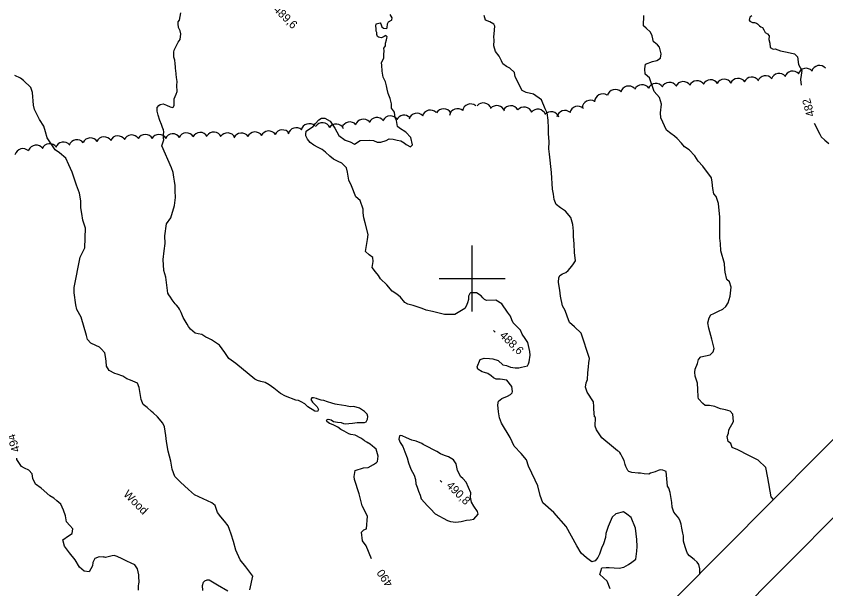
# Model space of a CAD drawing. Extents: x 642515 to 647219, y 6080136 to 6084356.
# Drawn here: x 644234.2 to 644528.9, y 6080687.3 to 6080895.6 of the extents above; entities that cross this region are included whole.
import ezdxf

# ---------------------------------------------------------------- set-up
doc = ezdxf.new("R2010")
doc.units = 0
for name, color, linetype in [('Level 1', 7, 'Continuous'), ('Level 2', 7, 'Continuous'), ('Level 3', 7, 'Continuous'), ('Level 44', 7, 'Continuous'), ('Level 60', 7, 'Continuous'), ('Level 61', 7, 'Continuous')]:
    doc.layers.add(name, color=color, linetype=linetype)

msp = doc.modelspace()

# ---------------------------------------------------------------- linework, layer by layer
at = {"layer": 'Level 1'}
for points in [[(644292.11, 6080878.36), (644291.9, 6080879.6), (644291.55, 6080880.67), (644291.57, 6080881.56), (644291.61, 6080881.6), (644291.63, 6080882.49), (644291.7, 6080883.26), (644293.17, 6080886.15), (644293.91, 6080887.16), (644294.09, 6080889.2), (644293.9, 6080890.28), (644293.33, 6080891.53), (644293.13, 6080892.85), (644293.2, 6080893.62), (644293.65, 6080894.14), (644294.16, 6080896.8)], [(644289.44, 6080794.85), (644288.65, 6080800.7), (644287.92, 6080803.15), (644287.74, 6080807.1), (644288.02, 6080810.19), (644288.4, 6080812.88), (644288.3, 6080815.7), (644288.9, 6080820.02), (644290.53, 6080822.23), (644291.77, 6080826.75), (644292.22, 6080829.69), (644292.06, 6080832.11), (644292.09, 6080834.05), (644291.82, 6080835.64), (644291.57, 6080837.08), (644291.38, 6080838.77), (644290.78, 6080840.5), (644287.22, 6080848.46), (644287.88, 6080850.69), (644287.8, 6080851.21), (644287.83, 6080852.63), (644287.9, 6080853.4), (644287.79, 6080854.4), (644287.61, 6080854.79), (644287.11, 6080856.21), (644286.52, 6080857.71), (644285.83, 6080859.6), (644285.49, 6080861.11), (644285.57, 6080862.41), (644286.08, 6080863.17), (644286.62, 6080863.53), (644287.7, 6080863.73), (644288.95, 6080863.24), (644290.2, 6080862.68), (644291.18, 6080862.42), (644291.49, 6080862.61), (644291.65, 6080863.3), (644291.69, 6080864.56), (644291.66, 6080865.57), (644292.48, 6080867.2), (644292.78, 6080868.22), (644292.67, 6080870.44), (644292.74, 6080871.9), (644292.52, 6080873.38), (644292.4, 6080874.54), (644292.39, 6080874.7), (644292.31, 6080875.83), (644292.22, 6080876.59), (644292.15, 6080877.11), (644292.11, 6080878.36)], [(644349.02, 6080754.76), (644347.45, 6080755.3), (644346.16, 6080755.74), (644345.22, 6080755.96), (644344.44, 6080756.11), (644343.7, 6080756.38), (644343.45, 6080756.53), (644342.42, 6080756.74), (644341.85, 6080756.78), (644341.49, 6080756.19), (644342.04, 6080755.18), (644342.99, 6080754.27), (644343.77, 6080753.44), (644344.2, 6080752.46), (644343.92, 6080751.79), (644342.9, 6080751.93), (644340.38, 6080753.45), (644339.21, 6080754.63), (644337.95, 6080755.35), (644336.95, 6080755.77), (644335.93, 6080755.9), (644332.16, 6080757.39), (644330.36, 6080758.28), (644327.97, 6080760.22), (644326.31, 6080761.52), (644324.84, 6080762.35), (644323.24, 6080762.69), (644322.05, 6080763.06), (644321.04, 6080763.56), (644314.16, 6080769.2), (644311.61, 6080771.13), (644310.18, 6080773.29), (644308.14, 6080775.98), (644305.23, 6080777.85), (644304.1, 6080778.46), (644303.18, 6080778.88), (644301.75, 6080779.76), (644300.48, 6080780.04), (644299.37, 6080780.33), (644297.66, 6080781.75), (644296.87, 6080782.74), (644296.4, 6080783.6), (644294.95, 6080786.01), (644294.27, 6080787.82), (644293.62, 6080788.99), (644293.3, 6080789.58), (644292.59, 6080790.5), (644292.04, 6080790.99), (644290.97, 6080792.45), (644290.42, 6080793.38), (644289.76, 6080794.27), (644289.44, 6080794.85)], [(644366, 6080735.57), (644365.19, 6080738.1), (644364.5, 6080738.71), (644363.9, 6080739.23), (644363.01, 6080739.86), (644362.42, 6080740.22), (644362.34, 6080740.3), (644361.83, 6080740.59), (644360.95, 6080741.13), (644360.4, 6080741.54), (644359.67, 6080742.1), (644357.58, 6080743.17), (644356.03, 6080743.39), (644355.21, 6080743.66), (644353.61, 6080744.6), (644352.39, 6080745.29), (644351.21, 6080746.1), (644349.82, 6080746.85), (644348.99, 6080747.2), (644348.29, 6080747.44), (644347.2, 6080748.09), (644347.14, 6080748.37), (644347.39, 6080748.83), (644347.79, 6080748.94), (644348.31, 6080748.93), (644348.8, 6080748.81), (644349.69, 6080748.18), (644351.16, 6080747.95), (644352.43, 6080747.76), (644353.34, 6080747.41), (644354.12, 6080747.26), (644355.24, 6080747.42), (644356.6, 6080747.59), (644358.32, 6080747.83), (644359.45, 6080747.82), (644359.82, 6080747.8), (644360.91, 6080747.76), (644361.54, 6080748.04), (644362.08, 6080749), (644362.14, 6080750.02), (644361.88, 6080750.85), (644361.01, 6080751.76), (644359.15, 6080753.01), (644357.14, 6080753.56), (644355.73, 6080753.51), (644354.17, 6080753.81), (644352.65, 6080754.15), (644351.02, 6080754.37), (644350.29, 6080754.48), (644349.02, 6080754.76)], [(644394.87, 6080730.31), (644394.39, 6080732.7), (644393.32, 6080734.24), (644391.48, 6080735.25), (644390.07, 6080735.72), (644388.57, 6080736.43), (644387.3, 6080737.24), (644385.8, 6080737.94), (644384.29, 6080738.81), (644382.29, 6080739.81), (644381.78, 6080740.1), (644379.79, 6080740.94), (644378.22, 6080741.4), (644376.23, 6080742.23), (644374.73, 6080742.94), (644374.23, 6080743.07), (644373.76, 6080742.88), (644373.51, 6080741.73), (644374, 6080740.55), (644374.91, 6080738.99), (644375.68, 6080737.11), (644376.55, 6080734.98), (644377, 6080733.08), (644377.87, 6080730.79), (644378.99, 6080728.6), (644379.58, 6080727.03), (644379.68, 6080725.42), (644380.17, 6080724.24), (644380.67, 6080722.74), (644381.25, 6080721.32), (644381.65, 6080720.06), (644383.93, 6080717.46), (644385.05, 6080716.33), (644386.63, 6080714.49), (644391.23, 6080712.13), (644392.3, 6080711.8), (644394.18, 6080711.52), (644396.18, 6080711.74), (644398.09, 6080712.19), (644399.46, 6080712.36), (644400.73, 6080712.61), (644402.31, 6080714.41), (644402.08, 6080715.36), (644400.82, 6080717.38), (644399.92, 6080718.77), (644399.56, 6080720.61), (644399.7, 6080722.15), (644397.98, 6080726.07), (644396.76, 6080727.45), (644396.07, 6080728.05), (644394.87, 6080730.31)], [(644363.48, 6080698.23), (644361.62, 6080702.89), (644360.21, 6080704.74), (644359.92, 6080707.87), (644360.67, 6080708.72), (644361.7, 6080709.04), (644362.12, 6080713.67), (644360.1, 6080717.41), (644358.99, 6080721.86), (644357.35, 6080727.08), (644357.2, 6080728.12), (644357.62, 6080730.33), (644360.55, 6080731.25), (644362.32, 6080731.37), (644364.26, 6080732.55), (644365.35, 6080733.27), (644365.73, 6080733.54), (644366, 6080735.57)]]:
    msp.add_lwpolyline(points, dxfattribs=at)
at = {"layer": 'Level 2'}
for points in [[(644372.13, 6080858.65), (644371.83, 6080860.74), (644370.84, 6080862.21), (644370.82, 6080863.75), (644370.37, 6080865.66), (644369.6, 6080867.55), (644369.26, 6080869.06), (644368.93, 6080870.26), (644368.59, 6080871.77), (644367.75, 6080873.41), (644367.44, 6080875.66), (644367.3, 6080877.75), (644367.17, 6080878.63), (644368.06, 6080880.43), (644368.05, 6080881.2), (644368.02, 6080881.69), (644368.09, 6080883.07), (644368.02, 6080884.03), (644368.4, 6080884.46), (644368.61, 6080884.88), (644368.67, 6080885.82), (644368.92, 6080886.97), (644369.08, 6080887.66), (644369.17, 6080888.11), (644368.69, 6080888.61), (644368.1, 6080888.29), (644367.21, 6080887.78), (644366.55, 6080887.9), (644366.1, 6080887.99), (644365.64, 6080888.24), (644365.51, 6080888.96), (644365.42, 6080889.73), (644365.23, 6080890.2), (644365.2, 6080891.21), (644365.1, 6080892.05), (644365.17, 6080892.83), (644366.73, 6080893.21), (644366.95, 6080892.86), (644367.16, 6080892.15), (644367.31, 6080891.71), (644367.91, 6080891.27), (644368.92, 6080891.21), (644369.23, 6080891.4), (644369.3, 6080892.86), (644369.66, 6080893.53), (644370.79, 6080894.13), (644370.94, 6080894.3), (644371.01, 6080895.08), (644370.25, 6080896.2)], [(644428.05, 6080847.41), (644428.13, 6080849.93), (644427.93, 6080853), (644427.89, 6080854.86), (644427.85, 6080857.77), (644427.44, 6080860.42), (644426.77, 6080861.91), (644425.42, 6080865.23), (644422.45, 6080867.22), (644419.81, 6080867.85), (644418.38, 6080868.65), (644415.86, 6080873.59), (644415.52, 6080875.11), (644413.87, 6080876.7), (644412.62, 6080877.34), (644411.34, 6080878.31), (644410.78, 6080879.41), (644409.94, 6080881.05), (644408.69, 6080882.75), (644408.07, 6080884.82), (644408.18, 6080886.85), (644408.09, 6080888.15), (644408.1, 6080889.2), (644408.4, 6080891.98), (644408.03, 6080892.76), (644406.6, 6080893.56), (644405.02, 6080894.18), (644404.58, 6080895.85)], [(644462.51, 6080892.12), (644462.59, 6080895.86)], [(644501.9, 6080895.82), (644501.16, 6080895.32), (644500.94, 6080894.21), (644501.25, 6080893.87), (644501.72, 6080893.53), (644502.22, 6080893.32), (644502.91, 6080893.33), (644503.62, 6080893.09), (644504, 6080892.83), (644504.7, 6080892.14), (644505.17, 6080891.81), (644505.76, 6080891.52), (644506.26, 6080890.7), (644506.81, 6080889.68), (644507.58, 6080889.17), (644508.24, 6080888.44), (644508.13, 6080887.09), (644508.53, 6080885.81), (644508.64, 6080884.2), (644509.66, 6080883.61), (644510.38, 6080883.74), (644512.38, 6080883.06), (644513.53, 6080882.81), (644514.85, 6080882.58), (644517.49, 6080881.94), (644518.54, 6080880.87), (644518.97, 6080878.05), (644520.09, 6080875.85), (644519.88, 6080874.21), (644519.66, 6080872.57), (644519.92, 6080870.49)], [(644509.86, 6080719.79), (644509, 6080720.78), (644507.73, 6080727.67), (644507, 6080731.36), (644504.22, 6080734.09), (644500.86, 6080735.82), (644496.83, 6080737.82), (644494.83, 6080738.66), (644494.25, 6080740.09), (644493.38, 6080740.84), (644493.02, 6080742.68), (644493.43, 6080743.85), (644493.59, 6080745.07), (644495.25, 6080748.19), (644495, 6080750.85), (644494.11, 6080751.93), (644492.38, 6080752.38), (644490.57, 6080752.75), (644489.56, 6080753.17), (644488.48, 6080753.66), (644486.59, 6080753.94), (644484.96, 6080754), (644484.1, 6080754.75), (644482.53, 6080756.43), (644482.4, 6080757.15), (644482.3, 6080759.82), (644482.15, 6080762.09), (644481.34, 6080764.63), (644481.24, 6080766.09), (644481.33, 6080767.23), (644482.17, 6080769.23), (644482.56, 6080770.72), (644483.39, 6080771.67), (644485.07, 6080772.02), (644486.75, 6080772.38), (644487.89, 6080773.51), (644488.22, 6080774.75), (644487.35, 6080778.1), (644486.27, 6080782.09), (644485.98, 6080784.02), (644486.35, 6080785.83), (644487.01, 6080786.93), (644488.11, 6080787.49), (644489.84, 6080788.25), (644491.42, 6080789.01), (644492.48, 6080790.05), (644493.29, 6080791.32), (644494.03, 6080793.73), (644494.37, 6080797.08), (644493.76, 6080798.98), (644492.81, 6080799.81), (644492.23, 6080802.45), (644492.16, 6080803.58), (644491.94, 6080805.6), (644490.66, 6080810.22), (644490.48, 6080812.97), (644490.35, 6080814.91), (644490.24, 6080817.91), (644490.27, 6080821.07), (644490.34, 6080822.54), (644489.77, 6080827.45), (644488.95, 6080830), (644488.15, 6080831), (644487.7, 6080832.92), (644487.46, 6080835.26), (644487.28, 6080836.79), (644484.16, 6080841.04), (644482.41, 6080842.87), (644481.23, 6080844.83), (644479.14, 6080846.96), (644477.44, 6080848.14), (644476.29, 6080849.45), (644474.72, 6080851.13), (644473.77, 6080851.96), (644472.49, 6080852.93), (644470.86, 6080854.2), (644468.86, 6080858.69), (644468.74, 6080860.47), (644469.03, 6080863.58), (644468.29, 6080866.04), (644466.44, 6080868.27), (644464.66, 6080873.19), (644463.1, 6080874.55), (644462.98, 6080876.49), (644463.27, 6080878.21), (644465.8, 6080879.19), (644467.32, 6080879.54), (644468.65, 6080880.36), (644468.95, 6080881.92), (644468.3, 6080884.31), (644467.59, 6080885.24), (644466.4, 6080886.13), (644466.14, 6080886.36), (644465.68, 6080888.44), (644465.1, 6080889.86), (644463.54, 6080891.22), (644462.51, 6080892.12)], [(644258.45, 6080821.36), (644258.04, 6080823.83), (644257.74, 6080825.91), (644257.73, 6080828.49), (644257.3, 6080831.28), (644256.15, 6080834.11), (644255.25, 6080836.71), (644254.62, 6080838.93), (644253.4, 6080841.51), (644252.27, 6080844.01), (644249.96, 6080845.88), (644248.36, 6080846.98), (644246.39, 6080849.91), (644245.49, 6080851.31), (644244.93, 6080853.61), (644244.31, 6080855.66), (644242.71, 6080857.98), (644241.79, 6080859.69), (644240.85, 6080861.72), (644240.5, 6080863.23), (644240.2, 6080867.89), (644239.51, 6080869.7), (644236.92, 6080872.27), (644235.82, 6080873.08), (644233.66, 6080874.07)], [(644360.49, 6080825.43), (644359.4, 6080828.51), (644357.76, 6080829.94), (644356.21, 6080833.88), (644355.26, 6080835.92), (644354.82, 6080838.89), (644354.39, 6080840.48), (644352.67, 6080842.14), (644351.33, 6080842.7), (644349.66, 6080843.56), (644348.37, 6080844.69), (644346.74, 6080846.12), (644345.53, 6080847.17), (644344.12, 6080847.8), (644342.52, 6080848.75), (644341.24, 6080849.72), (644340.27, 6080850.87), (644339.63, 6080852.04), (644339.58, 6080852.68), (644339.76, 6080853.74), (644340.61, 6080854.37), (644342.23, 6080855.53), (644343.13, 6080856.56), (644344.34, 6080857.93), (644345.35, 6080858.57), (644346.48, 6080858.48), (644348.42, 6080857.4), (644350.2, 6080854.93), (644351.67, 6080852.27), (644353.97, 6080850.57), (644355.8, 6080849.88), (644357.39, 6080849.09), (644359.41, 6080850.36), (644362.71, 6080850.5), (644364.26, 6080850.36), (644365.59, 6080849.8), (644366.97, 6080849.81), (644368.87, 6080850.43), (644369.97, 6080850.98), (644371.35, 6080850.83), (644372.91, 6080850.53), (644374.22, 6080850.3), (644375.4, 6080849.57), (644376.18, 6080848.89), (644377.77, 6080848.11), (644378.44, 6080848.88), (644377.86, 6080851.51), (644376.04, 6080853.41), (644373.68, 6080854.87), (644372.99, 6080855.48), (644372.6, 6080857.63), (644372.13, 6080858.65)], [(644524.63, 6080856.7), (644526.66, 6080852.71), (644527.14, 6080851.68), (644528.52, 6080850.48), (644529.98, 6080849.35)], [(644483.05, 6080692.8), (644482.99, 6080694.58), (644482.65, 6080696.1), (644482.03, 6080696.95), (644480.91, 6080697.93), (644479.2, 6080699.27), (644478.57, 6080700.12), (644478.1, 6080701.14), (644477.68, 6080702.57), (644477.06, 6080704.64), (644477.02, 6080706.5), (644476.79, 6080707.46), (644476.43, 6080709.3), (644476.17, 6080710.74), (644475.85, 6080711.93), (644475.37, 6080712.96), (644473.52, 6080715.18), (644472.92, 6080716.92), (644472.81, 6080718.7), (644472.55, 6080720.14), (644472.16, 6080722.3), (644471.73, 6080723.9), (644471.28, 6080724.6), (644470.77, 6080729.91), (644469.59, 6080730.48), (644468.62, 6080730.58), (644467.82, 6080730.36), (644466.72, 6080729.8), (644465.05, 6080729.29), (644464.5, 6080729.01), (644462.72, 6080729.05), (644461.41, 6080729.29), (644460.51, 6080729.31), (644458.31, 6080729.56), (644457.23, 6080729.9), (644456.8, 6080730.27), (644456.13, 6080731.77), (644455.84, 6080732.48), (644455.5, 6080734), (644454.77, 6080735.24), (644454.3, 6080736.27), (644453.93, 6080736.89), (644453.59, 6080737.19), (644453.08, 6080737.48), (644451.54, 6080738.68), (644447.34, 6080742.21), (644445.36, 6080745.15), (644444.86, 6080746.5), (644444.98, 6080749.58), (644444.64, 6080749.89), (644444.46, 6080752.63), (644444.39, 6080753.6), (644444.36, 6080755.3), (644442.02, 6080758.87), (644441.42, 6080760.61), (644441.63, 6080762.25), (644442.12, 6080763.49), (644442.21, 6080765.85), (644442.55, 6080767.98), (644442.62, 6080769.44), (644442.83, 6080771.08), (644439.79, 6080780.28), (644437.45, 6080782.63), (644435.56, 6080784.13), (644434.68, 6080786.42), (644433.97, 6080788.56), (644433.05, 6080790.28), (644432.26, 6080793.71), (644432.03, 6080795.89), (644431.86, 6080797.25), (644431.59, 6080798.86), (644431.65, 6080800.48), (644432.08, 6080801.32), (644433.01, 6080801.87), (644434.2, 6080802.35), (644435.04, 6080803.14), (644436.39, 6080804.69), (644437.07, 6080805.46), (644437.8, 6080806.65), (644437.44, 6080809.7), (644437.24, 6080812.77), (644437.06, 6080815.51), (644437.09, 6080817.46), (644436.77, 6080819.87), (644436.04, 6080822.33), (644434.1, 6080824.63), (644432.31, 6080825.89), (644430.69, 6080827.16), (644430, 6080828.98), (644429.71, 6080830.91), (644429.43, 6080832.67), (644429.03, 6080838.8), (644428.27, 6080845.4), (644428.05, 6080847.41)], [(644421.23, 6080772.27), (644421.14, 6080773.56), (644420.44, 6080776.91), (644419.45, 6080778.39), (644418.38, 6080779.93), (644417.8, 6080781.35), (644415.11, 6080784), (644414.55, 6080785.1), (644414.06, 6080786.44), (644412.99, 6080787.99), (644410.92, 6080791.01), (644408.82, 6080792.24), (644405.42, 6080792.18), (644404.67, 6080792.53), (644403.99, 6080793.13), (644403.45, 6080793.91), (644401.68, 6080795), (644399.57, 6080795.02), (644399.27, 6080794.68), (644398.76, 6080793.76), (644398.76, 6080792.54), (644398.44, 6080791.31), (644397.96, 6080790.06), (644397.44, 6080789.3), (644393.79, 6080787.03), (644390.14, 6080787.03), (644385.7, 6080788.19), (644383.4, 6080788.69), (644381.98, 6080789.32), (644378.67, 6080790.39), (644376.78, 6080790.83), (644375.69, 6080791.49), (644374.11, 6080793.33), (644372.73, 6080794.53), (644371.05, 6080795.55), (644369.11, 6080797.85), (644366.78, 6080800.04), (644366.05, 6080801.28), (644364.92, 6080802.58), (644363.76, 6080804.21), (644364.1, 6080806.33), (644364.01, 6080807.78), (644362.64, 6080808.82), (644361.35, 6080809.95), (644362.03, 6080814.37), (644362.31, 6080816.25), (644361.23, 6080820.38), (644360.7, 6080822.21), (644360.5, 6080824.06), (644360.49, 6080825.43)], [(644310.07, 6080711.89), (644308.68, 6080713.41), (644307.52, 6080715.03), (644306.62, 6080717.63), (644305.35, 6080718.59), (644299.11, 6080721.48), (644296.97, 6080723.36), (644294.04, 6080726.07), (644291.97, 6080728.19), (644290.98, 6080730.86), (644290.47, 6080733.73), (644289.51, 6080737.3), (644288.95, 6080740.81), (644288.64, 6080743.05), (644288.19, 6080746.16), (644287.62, 6080747.57), (644285.69, 6080749.86), (644284.06, 6080751.29), (644283.46, 6080751.81), (644281.84, 6080753.24), (644280.39, 6080754.35), (644279.71, 6080756.16), (644279.32, 6080758.31), (644279.01, 6080760.55), (644278.35, 6080762.04), (644275.86, 6080763.16), (644274.53, 6080763.72), (644273.02, 6080764.59), (644270.95, 6080765.33), (644270.13, 6080765.6), (644268.04, 6080766.67), (644267.04, 6080768.3), (644266.93, 6080770.07), (644266.65, 6080771.82), (644266.48, 6080773.18), (644265.17, 6080774.63), (644264.49, 6080775.23), (644263.16, 6080775.78), (644261.33, 6080776.63), (644260.11, 6080778), (644259.85, 6080779.43), (644257.88, 6080786.16), (644256.32, 6080788.88), (644255.89, 6080790.62), (644255.35, 6080795.02), (644255.31, 6080796.87), (644257.48, 6080807.99), (644259.19, 6080811.33), (644259.44, 6080818.52), (644258.45, 6080821.36)], [(644450.41, 6080687.24), (644449.33, 6080690), (644446.66, 6080692.5), (644447.39, 6080694.89), (644448.92, 6080695.07), (644449.97, 6080695.06), (644451.84, 6080694.94), (644453.71, 6080694.83), (644455.38, 6080695.18), (644457.1, 6080696.1), (644458.27, 6080696.91), (644459.73, 6080698.06), (644460.1, 6080700.92), (644460.23, 6080702.62), (644460.06, 6080705.2), (644459.63, 6080709.38), (644457.99, 6080713.23), (644456.46, 6080714.43), (644455.19, 6080715.23), (644452.48, 6080714.57), (644451.11, 6080713.34), (644449.63, 6080709.93), (644448.75, 6080707.36), (644448.69, 6080705.9), (644447.94, 6080703.66), (644447.25, 6080702), (644446.49, 6080699.93), (644445.93, 6080698.6), (644444.88, 6080697.39), (644443.69, 6080697.07), (644441.73, 6080698.48), (644439.83, 6080700.29), (644438.29, 6080702.86), (644434.42, 6080709.88), (644429.87, 6080715.08), (644425.92, 6080718.54), (644424.93, 6080721.22), (644424.05, 6080724.73), (644423.11, 6080726.77), (644420.66, 6080731.94), (644419.87, 6080734.16), (644417.93, 6080736.45), (644415.49, 6080739.2), (644413.98, 6080742.34), (644410.81, 6080747.55), (644410.11, 6080749.53), (644409.72, 6080751.68), (644409.48, 6080754.18), (644409.79, 6080755.57), (644410.94, 6080756.54), (644413.07, 6080757.41), (644414.16, 6080757.97), (644414.69, 6080758.57), (644414.82, 6080759.06), (644414.62, 6080760.91), (644412.77, 6080763.13), (644410.4, 6080763.54), (644409.75, 6080763.5), (644408.93, 6080763.61), (644407.94, 6080764.03), (644407.08, 6080764.78), (644405.81, 6080765.58), (644404.65, 6080765.99), (644403.75, 6080766.17), (644402.22, 6080767.2), (644402.01, 6080768), (644403.04, 6080770.74), (644404.54, 6080771.24), (644406.5, 6080771.05), (644407.64, 6080770.96), (644409.63, 6080770.29), (644411.34, 6080768.78), (644412.65, 6080768.55), (644414.07, 6080767.91), (644415.79, 6080767.62), (644417.08, 6080767.71), (644418.12, 6080767.86), (644419.24, 6080768.1), (644420.27, 6080768.41), (644420.63, 6080769.16), (644420.91, 6080769.83), (644421.23, 6080772.27)], [(644272.78, 6080698.19), (644270.95, 6080699.03), (644269.88, 6080699.37), (644269.17, 6080699.24), (644266.71, 6080698.67), (644265.97, 6080698.86), (644265.89, 6080698.78), (644264.36, 6080698.92), (644262.87, 6080698.25), (644262.08, 6080696.83), (644261.92, 6080695.61), (644260.77, 6080693.44), (644258.99, 6080693.65), (644257.28, 6080695.14), (644255.65, 6080697.77), (644253.63, 6080700.3), (644251.77, 6080702.83), (644251.14, 6080705.04), (644253.22, 6080706.55), (644254.53, 6080707.36), (644254.82, 6080709.07), (644253.78, 6080710.29), (644252.56, 6080711.66), (644252.17, 6080713.8), (644251.47, 6080715.93), (644250.44, 6080718.04), (644248.99, 6080719.31), (644247.88, 6080720.28), (644246.46, 6080721.07), (644243.29, 6080723.84), (644241.18, 6080725.39), (644240.32, 6080727.35), (644240.05, 6080729.1), (644238.83, 6080730.47), (644237.17, 6080731.16), (644236.17, 6080731.74), (644234.47, 6080734.28), (644234.49, 6080734.78)], [(644319.22, 6080686.94), (644320.35, 6080691.85), (644317.78, 6080695.31), (644315.68, 6080697.75), (644314.15, 6080701.36), (644313.3, 6080704.53), (644312.4, 6080707.13), (644311.8, 6080708.86), (644311.31, 6080710.2), (644310.07, 6080711.89)], [(644278.77, 6080686.75), (644278.74, 6080688.44), (644278.87, 6080688.93), (644278.98, 6080689.75), (644278.85, 6080691.67), (644278.81, 6080692.31), (644278.34, 6080694.53), (644277.35, 6080696), (644276.1, 6080696.64), (644274.45, 6080697.34), (644272.78, 6080698.19)], [(644302.14, 6080686.61), (644302.02, 6080688.53), (644302.42, 6080689.69), (644302.87, 6080690.2), (644303.65, 6080690.58), (644304.38, 6080690.55), (644307.49, 6080688.74), (644311.18, 6080686.56)]]:
    msp.add_lwpolyline(points, dxfattribs=at)
at = {"layer": 'Level 3'}
for p, q in [((644407.91, 6080781.26), (644408.48, 6080780.7)), ((644388.51, 6080726.63), (644389.08, 6080726.07))]:
    msp.add_line(p, q, dxfattribs=at)
at = {"layer": 'Level 44'}
for centre, start, end in [((644521.68, 6080873.68), 41.9879, 161.9658), ((644526.57, 6080874.71), 41.9879, 161.9658), ((644501.92, 6080870.46), 35.0887, 155.0667), ((644506.92, 6080870.95), 39.705, 159.6829), ((644511.85, 6080871.8), 39.705, 159.6829), ((644516.79, 6080872.64), 41.9879, 161.9658), ((644462.02, 6080867.72), 34.8826, 154.8605), ((644467, 6080868.15), 34.8826, 154.8605), ((644471.98, 6080868.51), 33.8116, 153.7896), ((644476.97, 6080868.84), 33.8508, 153.8288), ((644481.96, 6080869.17), 33.8508, 153.8288), ((644486.94, 6080869.5), 32.436, 152.4139), ((644491.94, 6080869.71), 32.436, 152.4139), ((644496.94, 6080870.02), 35.0887, 155.0667), ((644452.27, 6080865.94), 44.9235, 164.9014), ((644457.1, 6080867.22), 44.9235, 164.9014), ((644443.18, 6080862.06), 57.1912, 177.1691), ((644447.63, 6080864.34), 57.1912, 177.1691), ((644389.79, 6080858.92), 29.6488, 149.6268), ((644394.88, 6080858.99), 50.3237, 170.3017), ((644399.57, 6080860.72), 50.3237, 170.3017), ((644404.21, 6080861.07), 18.972, 138.95), ((644409.12, 6080860.11), 18.972, 138.95), ((644414.17, 6080860.06), 31.0076, 150.9855), ((644419.08, 6080859.6), 20.559, 140.537), ((644424.01, 6080858.78), 20.559, 140.537), ((644438.64, 6080859.86), 47.9, 167.878), ((644365.46, 6080855.8), 37.1003, 157.0782), ((644370.4, 6080856.38), 32.5862, 152.5642), ((644375.39, 6080856.6), 45.9364, 152.5642), ((644380.06, 6080857.29), 43.5357, 163.5136), ((644384.92, 6080858.46), 43.5357, 163.5136), ((644428.91, 6080857.87), 18.8753, 138.8533), ((644433.89, 6080858.32), 47.9, 167.878), ((644340.86, 6080853.52), 47.187, 167.1649), ((644345.65, 6080853.83), 24.9959, 144.9738), ((644350.63, 6080853.39), 24.9959, 144.9738), ((644355.63, 6080854.15), 41.6759, 161.6539), ((644360.52, 6080855.16), 41.6759, 161.6539), ((644291.19, 6080849.82), 34.0658, 154.0438), ((644296.18, 6080850.18), 34.0658, 154.0438), ((644301.16, 6080850.33), 31.6868, 151.6647), ((644306.13, 6080850.46), 26.4274, 146.4054), ((644311.12, 6080850.15), 26.4274, 146.4054), ((644316.15, 6080850.12), 34.4478, 154.4258), ((644321.14, 6080850.5), 34.4478, 154.4258), ((644326.12, 6080850.89), 34.42, 154.398), ((644331.11, 6080851.27), 34.42, 154.398), ((644336.09, 6080852.05), 47.187, 167.1649), ((644251.39, 6080846.83), 39.7975, 159.7754), ((644256.32, 6080847.68), 39.7975, 159.7754), ((644261.24, 6080848.35), 34.2436, 154.2215), ((644266.23, 6080848.72), 34.2436, 154.2215), ((644271.21, 6080849.08), 33.8695, 153.8475), ((644276.2, 6080849.42), 33.8695, 153.8475), ((644281.18, 6080849.6), 30.2588, 150.2368), ((644286.18, 6080849.62), 30.2588, 150.2368), ((644236.66, 6080844.44), 45.6929, 165.6709), ((644241.44, 6080845.7), 36.0783, 156.0562), ((644246.41, 6080846.23), 36.0783, 156.0562)]:
    msp.add_arc(centre, 3, start, end, dxfattribs=at)
at = {"layer": 'Level 60'}
for points in [[(643756.23, 6083485.06), (645517.55, 6081734.46), (644300.6, 6080509.08), (642538.79, 6082260.16)], [(645532.22, 6081719.89), (645869.07, 6081384.98), (644651.68, 6080160.13), (644314.78, 6080494.98)]]:
    msp.add_lwpolyline(points, close=True, dxfattribs=at)
at = {"layer": 'Level 61'}
for p, q in [((644400, 6080812.16), (644400, 6080788.16)), ((644412.16, 6080800), (644388.16, 6080800))]:
    msp.add_line(p, q, dxfattribs=at)

# ---------------------------------------------------------------- texts
at = {"layer": 'Level 1'}
msp.add_text('490', height=3, rotation=124.813, dxfattribs=at).set_placement((644371.47, 6080689.22))
at = {"layer": 'Level 2'}
for s, rotation, p in [('482', 105.6579, (644524.87, 6080859.51)), ('494', 107.4565, (644235.63, 6080737.51))]:
    msp.add_text(s, height=3, rotation=rotation, dxfattribs=at).set_placement(p)
at = {"layer": 'Level 3'}
for s, p in [('489,6', (644327.62, 6080897.8)), ('488,6', (644409.94, 6080779.21)), ('490,8', (644390.54, 6080724.58))]:
    msp.add_text(s, height=3, rotation=315.59, dxfattribs=at).set_placement(p)
at = {"layer": 'Level 44'}
msp.add_text('Wood', height=3, rotation=315.1749, dxfattribs=at).set_placement((644272.99, 6080721.43))

doc.saveas('drawing.dxf')
